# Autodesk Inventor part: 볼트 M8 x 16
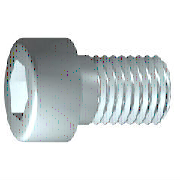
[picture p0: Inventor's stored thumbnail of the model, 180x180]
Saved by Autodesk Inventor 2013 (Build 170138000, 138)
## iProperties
IsCustomPart: 1
Created: 2012-02
Part Number: 볼트 M8 x 16
Material: 강철, 연강
Description: 원통형 머리 캡 나사
Document SubType Name: Modeling
Standard: JIS B 1176
Designer: mdu-01
Standards Organization: JIS
Language: ko-KR
Size Designation: M8 x 16
Categories: <MemberInstance><Categories><Category DisplayName="조임쇠" InternalName="e4da775c-781d-43d5-af7c-5136215cf5a6" Mnemonic="FSTN"><Category DisplayName="볼트" InternalN
Density: 1 g/cm^3
Author: mdu-01
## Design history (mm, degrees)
sketch "스케치1"
  geometry: L1 (-2, 0)-(16, 0); L2 (16, 0)-(16, 4); L3 (16, 4)-(3.125, 4); L4 (3.125, 4)-(2.358, 4); L5 (2.358, 4)-(0, 4); L6 (0, 4)-(0, 6.5); L7 (0, 6.5)-(-8, 6.5); L8 (-8, 6.5)-(-8, 3.464); L9 (-8, 3.464)-(-4, 3.464); L10 (-4, 3.464)-(-2, 0); L11 (-12.8, 0)-(20.8, 0) reference; L12 (0, -1.3)-(0, 7.8) reference; L13 (3.125, 4)-(0, 4)
  constraints: 22 end point, 6 parallel, 2 collinear, 2 perpendicular, 1 horizontal, 1 point on line
  dimensions: "d1" = 12.875 distance from line of L3.end L2 (= GEL); "d2" = 0.76691 distance of L4.end L3.end (computed from GAL); "d3" = 8 distance between parallel lines of L8 L6 (= KOH); "d4" = 4 distance of L8.end L9.end (= INTI); "d5" = 60 deg angle of L10 L1; "d6" = 8 diameter of L3 L1 (= GD); "d7" = 8 diameter of L5 L1 (= BDM); "d8" = 6.9282 diameter of L9 L1 (= 1.1547 x SW); "d9" = 13 diameter of L7 L1 (= KOD); "d26" = 16 distance between parallel lines of L12 L2 (= NLG)
revolve "본체" sketch "스케치1" stored, may be unused: angle "d10" = 90 deg
sketch "스케치2"
  geometry: L1 (0, -9.1)-(0, 9.1) reference; L2 (-9.1, 0)-(9.1, 0) reference; L3 (3.464, 0)-(1.732, -3); L4 (1.732, -3)-(-1.732, -3); L5 (-1.732, -3)-(-3.464, 0); L6 (-3.464, 0)-(-1.732, 3); L7 (-1.732, 3)-(1.732, 3); L8 (1.732, 3)-(3.464, 0); 2 further points
  constraints: 12 end point, 1 coincident, 1 horizontal alignment, 1 point on line, 12 other
extrude "슬롯" join sketch "스케치2" stored distance "d11" = 10; taper "d12" = 0 deg
workplane "Work Plane1"
fillet "Fillet2" dims "d30" = 0.1 (= R)
body "Solid1"
fillet "모깎기1" dims "d17" = 0.8 (= RR)
feature "스레드" dims "d13" = 12.875 (= GEL), "d14" = 0
chamfer "모따기1" distance "d15" = 0.76681 (= -0.5 x SPD + 0.5 x GD); stored, may be unused: second distance "d16" = 0.76681 (= GUL), angle "d27" = 45 deg
other parameters: "GD" = 8 (= NND) [user parameter; used in 2 equation terms], "NLG" = 16 [user parameter; used in 1 equation term], "GEL" = 12.875 [user parameter; used in 2 equation terms], "KOD" = 13 [user parameter; used in 1 equation term], "KOH" = 8 [user parameter; used in 1 equation term], "INTI" = 4 [user parameter; used in 1 equation term], "GAL" = 0.76681 (= 0.61345 x PTC) [user parameter; used in 1 equation term], "GUL" = 0.76681 (= 0.61345 x PTC) [user parameter; used in 1 equation term], "BDM" = 8 (= NND) [user parameter; used in 1 equation term], "SW" = 6 [user parameter; used in 2 equation terms], "RR" = 0.8 [user parameter; used in 1 equation term], "SPD" = 6.46637 (= NND - 1.2269 x PTC) [user parameter; used in 1 equation term], "d19" = 0, "d28" = 0, "d29" = 0, "R" = 0.1 [user parameter; used in 1 equation term], "PHH" = 0.4 [user parameter], "GD1" = 6.46637 (= THREADDIA - 1.2269 x PTC) [user parameter], "THREADDIA" = 8 [user parameter; used in 1 equation term], "FAWI" = 45 deg [user parameter], "TPU" = 8 (computed from PTC) [user parameter], "PTC" = 1.25 [user parameter; used in 5 equation terms], "NND" = 8 [user parameter; used in 3 equation terms], "TOA" = 30 deg [user parameter], "E0" = 6.93 (= 1.155 x SW) [user parameter]
